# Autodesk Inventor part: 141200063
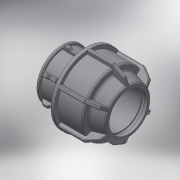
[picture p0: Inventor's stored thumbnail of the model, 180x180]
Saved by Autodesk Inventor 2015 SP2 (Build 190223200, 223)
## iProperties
Created: 2017-08
Part Number: 141200063
Material: Generic
Description: PLASSON L.14 END PLUG (SILVER) 63
Document SubType Name: Modeling
Designer: KIM
Density: 1 g/cm^3
Appearance: Default
Author: KIM
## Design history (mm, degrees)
derived "141200.ipt"
feature "Solid1::141200.ipt"
tag "TaggingFeature1"
body "Solid1"
other parameters: "d1" = 63, "d4" = 15 deg, "d5" = 52.8, "d6" = 17.424, "d10" = 105, "d16" = 64.26, "d17" = 4, "d18" = 112, "d22" = 75.6, "d24" = 4, "d25" = 94.5, "d26" = 78.75, "d27" = 4, "d28" = 135 deg, "d29" = 2.4, "d31" = 3.15, "d44" = 1.26, "d46" = 150 deg, "d49" = 5.25, "d50" = 0, "d51" = 3.15, "d52" = 2.1, "d53" = 45 deg, "d54" = 22.4, "d55" = 8.96, "d56" = 5.25, "d57" = 0, "d58" = 1.89, "d59" = 1.26, "d61" = 360 deg, "d66" = 81.9, "d69" = 3.36, "d_" = 63, "E_" = 105, "H_" = 112
